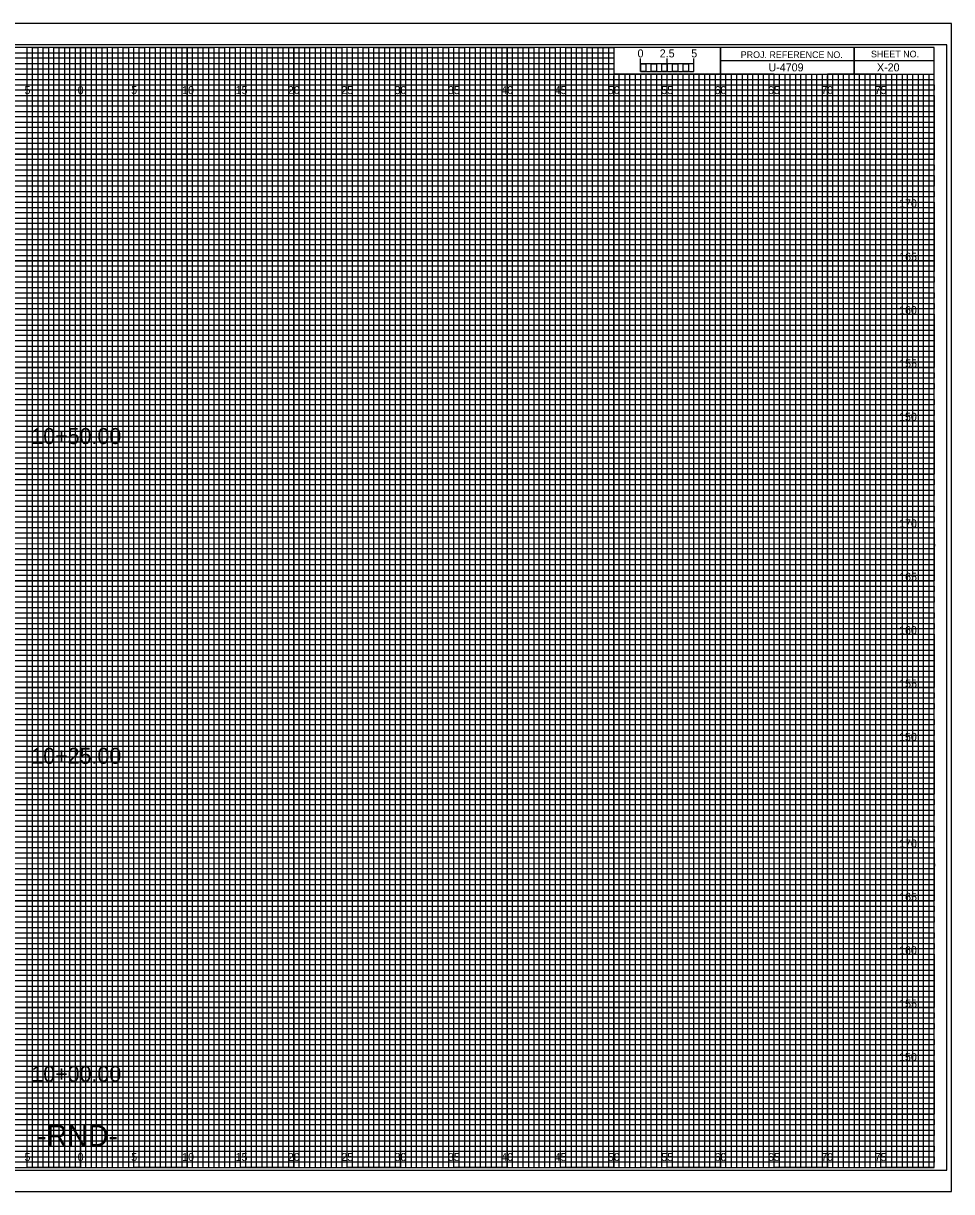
# Model space of a CAD drawing. Extents: x -7 to 162, y -2 to 107.
# Drawn here: x 74.6 to 161.7, y -2.3 to 107.3 of the extents above; entities that cross this region are included whole.
import ezdxf

# ---------------------------------------------------------------- set-up
doc = ezdxf.new("R2010")
doc.units = 0
for name, color, linetype in [('Prop XS Alignment Label', 7, 'Continuous'), ('Prop XS Bar Scale Labels', 7, 'Continuous'), ('Prop XS Elevation Labels', 7, 'Continuous'), ('Prop XS Label Text', 7, 'Continuous'), ('Prop XS Project Number', 7, 'Continuous'), ('Prop XS Sheet Number', 7, 'Continuous'), ('Prop XS Station Labels', 7, 'Continuous'), ('Sheet Cross Section CELL', 7, 'Continuous'), ('Sheet Cross Section Grid Major CELL', 7, 'Continuous'), ('Sheet Cross Section Grid Middle CELL', 7, 'Continuous'), ('Sheet Cross Section Grid Minor 1 CELL', 7, 'Continuous'), ('Sheet Cross Section Grid Minor 2 CELL', 7, 'Continuous'), ('Sheet Cross Section Scale CELL', 7, 'Continuous'), ('Sheet Cutting Line CELL', 7, 'Continuous'), ('Sheet DOT Grid CELL', 7, 'Continuous'), ('Sheet Plot Border Inside CELL', 7, 'Continuous'), ('Sheet Plot Border Outside CELL', 7, 'Continuous')]:
    doc.layers.add(name, color=color, linetype=linetype)

msp = doc.modelspace()

# ---------------------------------------------------------------- linework, layer by layer
at = {"layer": 'Sheet Cross Section CELL'}
for p, q in [((152.5, 105), (152.5, 102.5)), ((152.5, 102.5), (152.5, 105)), ((160, 103.75), (140, 103.75)), ((140, 103.75), (140, 102.5)), ((140, 102.5), (160, 102.5))]:
    msp.add_line(p, q, dxfattribs=at)
for points in [[(160, 105), (0, 105), (0, 0), (160, 0)], [(140, 105), (130, 105), (130, 102.52), (140, 102.52)], [(160, 105), (140, 105), (140, 102.5), (160, 102.5)]]:
    msp.add_lwpolyline(points, close=True, dxfattribs=at)
at = {"layer": 'Sheet Cross Section Grid Major CELL'}
for p, q in [((75, 105), (70, 105)), ((75, 0), (75, 105)), ((85, 105), (80, 105)), ((80, 105), (80, 0)), ((85, 0), (85, 105)), ((95, 105), (90, 105)), ((90, 105), (90, 0)), ((95, 0), (95, 105)), ((105, 105), (100, 105)), ((100, 105), (100, 0)), ((105, 0), (105, 105)), ((115, 105), (110, 105)), ((110, 105), (110, 0)), ((115, 0), (115, 105)), ((125, 105), (120, 105)), ((120, 105), (120, 0)), ((125, 0), (125, 105)), ((130, 105), (130, 0)), ((135, 0), (135, 102.5)), ((145, 102.5), (140, 102.5)), ((140, 102.5), (140, 0)), ((145, 0), (145, 102.5)), ((155, 102.5), (150, 102.5)), ((150, 102.5), (150, 0)), ((155, 0), (155, 102.5)), ((80, 0), (75, 0)), ((90, 0), (85, 0)), ((100, 0), (95, 0)), ((110, 0), (105, 0)), ((120, 0), (115, 0)), ((130, 0), (125, 0)), ((140, 0), (135, 0)), ((150, 0), (145, 0)), ((160, 0), (155, 0)), ((160, 0), (160, 0))]:
    msp.add_line(p, q, dxfattribs=at)
for points in [[(0, 100), (160, 100), (160, 95), (0, 95)], [(0, 90), (160, 90), (160, 85), (0, 85)], [(0, 80), (160, 80), (160, 75), (0, 75)], [(0, 70), (160, 70), (160, 65), (0, 65)], [(0, 60), (160, 60), (160, 55), (0, 55)], [(0, 50), (160, 50), (160, 45), (0, 45)], [(0, 40), (160, 40), (160, 35), (0, 35)], [(0, 30), (160, 30), (160, 25), (0, 25)], [(0, 20), (160, 20), (160, 15), (0, 15)], [(0, 10), (160, 10), (160, 5), (0, 5)]]:
    msp.add_lwpolyline(points, dxfattribs=at)
at = {"layer": 'Sheet Cross Section Grid Middle CELL'}
for points in [[(72.5, 0), (77.5, 0), (77.5, 105), (82.5, 105), (82.5, 0), (87.5, 0), (87.5, 105), (92.5, 105), (92.5, 0), (97.5, 0), (97.5, 105), (102.5, 105), (102.5, 0), (107.5, 0), (107.5, 105), (112.5, 105), (112.5, 0), (117.5, 0), (117.5, 105), (122.5, 105), (122.5, 0), (127.5, 0), (127.5, 105), (129.97, 105), (130, 105), (130, 102.5), (132.5, 102.5), (132.5, 0), (137.5, 0), (137.5, 102.5), (142.5, 102.5), (142.5, 0), (147.5, 0), (147.5, 102.5), (152.5, 102.5), (152.5, 0), (157.5, 0), (157.5, 102.5)], [(0, 102.5), (137.5, 102.5)], [(0, 92.5), (160, 92.5), (160, 97.5), (0, 97.5)], [(0, 82.5), (160, 82.5), (160, 87.5), (0, 87.5)], [(0, 72.5), (160, 72.5), (160, 77.5), (0, 77.5)], [(0, 62.5), (160, 62.5), (160, 67.5), (0, 67.5)], [(0, 52.5), (160, 52.5), (160, 57.5), (0, 57.5)], [(0, 42.5), (160, 42.5), (160, 47.5), (0, 47.5)], [(0, 32.5), (160, 32.5), (160, 37.5), (0, 37.5)], [(0, 22.5), (160, 22.5), (160, 27.5), (0, 27.5)], [(0, 12.5), (160, 12.5), (160, 17.5), (0, 17.5)], [(0, 2.5), (160, 2.5), (160, 7.5), (0, 7.5)]]:
    msp.add_lwpolyline(points, dxfattribs=at)
at = {"layer": 'Sheet Cross Section Grid Minor 1 CELL'}
for p, q in [((0, 104.5), (130, 104.5)), ((130, 104.5), (130, 103.99)), ((130, 103.99), (0, 103.99)), ((0, 103.5), (130, 103.5)), ((130, 102.95), (0, 102.95)), ((130, 103.5), (130, 102.95)), ((0, 102), (160, 102))]:
    msp.add_line(p, q, dxfattribs=at)
for points in [[(0, 101.5), (135, 101.5), (160, 101.5), (160, 101), (0, 101)], [(0, 100.5), (160, 100.5), (160, 99.5), (0, 99.5)], [(0, 99), (160, 99), (160, 98.5), (0, 98.49)], [(0, 98), (160, 98), (160, 97), (0, 97)], [(0, 96.5), (160, 96.5), (160, 96), (0, 96)], [(0, 95.5), (160, 95.5), (160, 94.5), (0, 94.5)], [(0, 94), (160, 94), (160, 93.5), (0, 93.5)], [(0, 93), (160, 93), (160, 92), (0, 92)], [(0, 91.5), (160, 91.5), (160, 91), (0, 91)], [(0, 90.5), (160, 90.5), (160, 89.5), (0, 89.5)], [(0, 89), (160, 89), (160, 88.5), (0, 88.5)], [(0, 88), (160, 88), (160, 86.98), (160, 86.5), (160, 86), (0, 86)], [(0, 87), (160, 87), (160, 86.5), (0, 86.5)], [(0, 85.5), (160, 85.5), (160, 84.5), (0, 84.52)], [(0, 84.52), (160, 84.5), (160, 84), (0, 84)], [(0, 83.5), (160, 83.5), (160, 83), (0, 83)], [(0, 82), (160, 82), (160, 81.5), (0, 81.5)], [(0, 81), (160, 81), (160, 80.5), (0, 80.5)], [(-0.04, 79.45), (160, 79.45), (160, 78.94), (-0.04, 78.94)], [(0, 78.5), (160, 78.5), (160, 78), (0, 78)], [(0, 77), (160, 77), (160, 76.5), (0, 76.5)], [(0, 76), (160, 76), (160, 75.5), (0, 75.5)], [(0, 74.5), (160, 74.5), (160, 74), (0, 74)], [(0, 73.5), (160, 73.5), (160, 73), (0, 73)], [(0, 72), (160, 72), (160, 71.5), (0, 71.5)], [(0, 71), (160, 71), (160, 70.5), (0, 70.5)], [(0, 69.5), (160, 69.5), (160, 68.99), (0, 69)], [(0, 68.5), (160, 68.5), (160, 68), (0, 68)], [(0, 67), (160, 67), (160, 66.5), (0, 66.5)], [(0, 66), (160, 66), (160, 65.5), (0, 65.5)], [(0, 64.5), (160, 64.5), (160, 64), (0, 64)], [(0, 63.5), (160, 63.5), (160, 63), (0, 63)], [(0, 62), (160, 62), (160, 61.5), (0, 61.5)], [(0, 61), (160, 61), (160, 60.5), (0, 60.5)], [(0, 59.5), (160, 59.5), (160, 59), (0, 59)], [(0, 58.5), (160.03, 58.45), (160, 58), (0, 58)], [(0, 57), (160, 57), (160, 56.5), (0, 56.5)], [(0, 56), (160, 56), (160, 55.5), (0, 55.5)], [(0, 54.5), (160, 54.5), (160, 54), (0, 54)], [(0, 53.5), (160, 53.5), (160, 53), (0, 53)], [(0, 52), (160, 52), (160, 51.5), (0, 51.5)], [(0, 51), (160, 51), (160, 50.5), (0, 50.5)], [(0, 49.5), (160, 49.5), (160, 49), (0, 49)], [(0, 48.5), (160, 48.5), (160, 48), (0, 48)], [(0, 47), (160, 47), (160, 46.5), (0, 46.5)], [(0, 46), (160, 46), (160, 45.5), (0, 45.5)], [(0, 44.5), (160, 44.5), (160, 44), (0, 44)], [(0, 43.5), (160, 43.5), (160, 43), (0, 43)], [(0, 42), (160, 42), (160, 41.5), (0, 41.5)], [(0, 41), (160, 41), (160, 40.5), (0, 40.5)], [(0, 39.5), (160, 39.5), (160, 38.99), (0, 39)], [(0, 38.5), (160, 38.5), (160, 38), (0, 38)], [(0, 37), (160, 37), (160, 36.5), (0, 36.5)], [(0, 36), (160, 36), (160, 35.5), (0, 35.5)], [(0, 34.5), (160, 34.5), (160, 34), (0, 34)], [(0, 33.5), (160, 33.5), (160, 33), (0, 33)], [(0, 32), (160, 32), (160, 31.5), (0, 31.5)], [(0, 31), (160, 31), (160, 30.5), (0, 30.5)], [(0, 29.5), (160, 29.5), (160, 29), (0, 29)], [(0, 28.5), (160.03, 28.46), (160, 28), (0, 28)], [(0, 27), (160, 27), (160, 26.5), (0, 26.5)], [(0, 26), (160, 26), (160, 25.5), (0, 25.5)], [(0, 24.5), (160, 24.5), (160, 24), (0, 24)], [(0, 23.5), (160, 23.5), (160, 23), (0, 23)], [(0, 22), (160, 22), (160, 21.5), (0, 21.5)], [(0, 21), (160, 21), (160, 20.5), (0, 20.5)], [(0, 19.5), (160, 19.5), (160, 19), (0, 19)], [(0, 18.5), (160, 18.5), (160, 18), (0, 18)], [(0, 17), (160, 17), (160, 16.5), (0, 16.5)], [(0, 16), (160, 16), (160, 15.5), (0, 15.5)], [(0, 14.5), (160, 14.5), (160, 14), (0, 14)], [(0, 13.5), (160, 13.5), (160, 13), (0, 13)], [(0, 12), (160, 12), (160, 11.5), (0, 11.5)], [(0, 11), (160, 11), (160, 10.5), (0, 10.5)], [(0, 9.5), (160, 9.5), (160, 9), (0, 9)], [(0, 8.5), (160, 8.5), (160, 8), (0, 8)], [(0, 7), (160, 7), (160, 6.5), (0, 6.5)], [(0, 6), (160, 6), (160, 5.5), (0, 5.5)], [(0, 4.5), (160, 4.5), (160, 4), (0, 4)], [(0, 3.5), (160, 3.5), (160, 3), (0, 3)], [(0, 2), (160, 2), (160, 1.5), (0, 1.5)], [(0, 1), (160, 1), (160, 0.5), (0, 0.5)]]:
    msp.add_lwpolyline(points, dxfattribs=at)
at = {"layer": 'Sheet Cross Section Grid Minor 2 CELL'}
for p, q in [((133.5, 102.5), (133, 102.5)), ((133, 102.5), (133, 0)), ((133.5, 0), (133.5, 102.5)), ((134.5, 102.5), (134, 102.5)), ((134, 102.5), (134, 0)), ((134.5, 0), (134.5, 102.5)), ((133, 0), (132.5, 0)), ((134, 0), (133.5, 0))]:
    msp.add_line(p, q, dxfattribs=at)
for points in [[(75, 0), (75.5, 0), (75.5, 105), (76, 105), (76, 0)], [(76, 0), (76.5, 0), (76.5, 105), (77, 105), (77, 0)], [(77.5, 0), (78, 0), (78, 105), (78.5, 105), (78.5, 0)], [(78.5, 0), (79, 0), (79, 105), (79.5, 105), (79.5, 0)], [(80, 0), (80.5, 0), (80.5, 105), (81, 105), (81, 0)], [(81, 0), (81.5, 0), (81.5, 105), (82, 105), (82, 0)], [(82.5, 0), (83, 0), (83, 105), (83.5, 105), (83.5, 0)], [(83.5, 0), (84, 0), (84, 105), (84.5, 105), (84.5, 0)], [(85, 0), (85.5, 0), (85.5, 105), (86, 105), (86, 0)], [(86, 0), (86.5, 0), (86.5, 105), (87, 105), (87, 0)], [(87.5, 0), (88, 0), (88, 105), (88.5, 105), (88.5, 0)], [(88.5, 0), (89, 0), (89, 105), (89.5, 105), (89.5, 0)], [(90, 0), (90.5, 0), (90.5, 105), (91, 105), (91, 0)], [(91, 0), (91.5, 0), (91.5, 105), (92, 105), (92, 0)], [(92.5, 0), (93, 0), (93, 105), (93.5, 105), (93.5, 0)], [(93.5, 0), (94, 0), (94, 105), (94.5, 105), (94.5, 0)], [(95, 0), (95.5, 0), (95.5, 105), (96, 105), (96, 0)], [(96, 0), (96.5, 0), (96.5, 105), (97, 105), (97, 0)], [(97.5, 0), (98, 0), (98, 105), (98.5, 105), (98.5, 0)], [(98.5, 0), (99, 0), (99, 105), (99.5, 105), (99.5, 0)], [(100, 0), (100.5, 0), (100.5, 105), (101, 105), (101, 0)], [(101, 0), (101.5, 0), (101.5, 105), (102, 105), (102, 0)], [(102.5, 0), (103, 0), (103, 105), (103.5, 105), (103.5, 0)], [(103.5, 0), (104, 0), (104, 105), (104.5, 105), (104.5, 0)], [(105, 0), (105.5, 0), (105.5, 105), (106, 105), (106, 0)], [(106, 0), (106.5, 0), (106.5, 105), (107, 105), (107, 0)], [(107.5, 0), (108, 0), (108, 105), (108.5, 105), (108.5, 0)], [(108.5, 0), (109, 0), (109, 105), (109.5, 105), (109.5, 0)], [(110, 0), (110.5, 0), (110.5, 105), (111, 105), (111, 0)], [(111, 0), (111.5, 0), (111.5, 105), (112, 105), (112, 0)], [(112.5, 0), (113, 0), (113, 105), (113.5, 105), (113.5, 0)], [(113.5, 0), (114, 0), (114, 105), (114.5, 105), (114.5, 0)], [(115, 0), (115.5, 0), (115.5, 105), (116, 105), (116, 0)], [(116, 0), (116.5, 0), (116.5, 105), (117, 105), (117, 0)], [(117.5, 0), (118, 0), (118, 105), (118.5, 105), (118.5, 0)], [(118.5, 0), (119, 0), (119, 105), (119.5, 105), (119.5, 0)], [(120, 0), (120.5, 0), (120.5, 105), (121, 105), (121, 0)], [(121, 0), (121.5, 0), (121.5, 105), (122, 105), (122, 0)], [(122.5, 0), (123, 0), (123, 105), (123.5, 105), (123.5, 0)], [(123.5, 0), (124, 0), (124, 105), (124.5, 105), (124.5, 0)], [(125, 0), (125.5, 0), (125.5, 105), (126, 105), (126, 0)], [(126, 0), (126.5, 0), (126.5, 105), (127, 105), (127, 0)], [(127.5, 0), (128, 0), (128, 105), (128.5, 105), (128.5, 0)], [(128.5, 0), (129, 0), (129, 105), (129.5, 105), (129.5, 0)], [(130, 0), (130.5, 0), (130.5, 102.5), (131.01, 102.5), (131.01, 0)], [(131, 0), (131.5, 0), (131.5, 102.5), (132, 102.5), (132, 0)], [(135, 0), (135.49, 0), (135.49, 102.5), (136, 102.5), (136, 0)], [(136, 0), (136.5, 0), (136.5, 102.5), (137.03, 102.5), (137.03, 0)], [(137.5, 0), (138, 0), (138, 102.5), (138.5, 102.5), (138.5, 0)], [(138.5, 0), (139, 0), (139, 102.5), (139.5, 102.5), (139.5, 0)], [(140, 0), (140.5, 0), (140.5, 102.5), (141, 102.5), (141, 0)], [(141, 0), (141.5, 0), (141.5, 102.5), (142, 102.5), (142, 0)], [(142.5, 0), (143, 0), (143, 102.5), (143.5, 102.5), (143.5, 0)], [(143.5, 0), (144, 0), (144, 102.5), (144.5, 102.5), (144.5, 0)], [(145, 0), (145.5, 0), (145.5, 102.5), (146, 102.5), (146, 0)], [(146, 0), (146.5, 0), (146.5, 102.5), (147, 102.5), (147, 0)], [(147.5, 0), (148, 0), (148, 102.5), (148.5, 102.5), (148.5, 0)], [(148.5, 0), (149, 0), (149, 102.5), (149.5, 102.5), (149.5, 0)], [(150, 0), (150.5, 0), (150.5, 102.5), (151, 102.5), (151, 0)], [(151, 0), (151.5, 0), (151.5, 102.5), (152, 102.5), (152, 0)], [(152.5, 0), (153, 0), (153, 102.5), (153.5, 102.5), (153.5, 0)], [(153.5, 0), (154, 0), (154, 102.5), (154.5, 102.5), (154.5, 0)], [(155, 0), (155.5, 0), (155.5, 102.5), (156, 102.5), (156, 0)], [(156, 0), (156.5, 0), (156.5, 102.5), (157, 102.5), (157, 0)], [(157.5, 0), (158, 0), (158, 102.5), (158.5, 102.5), (158.5, 0)], [(158.5, 0), (159, 0), (159, 102.5), (159.5, 102.5), (159.5, 0)]]:
    msp.add_lwpolyline(points, dxfattribs=at)
at = {"layer": 'Sheet Cross Section Scale CELL'}
for p, q in [((132.5, 102.75), (132.5, 103.95)), ((132.5, 103.45), (132.5, 103.95)), ((135, 102.75), (135, 103.95)), ((137.5, 102.75), (137.5, 103.95)), ((137.5, 103.45), (137.5, 103.95))]:
    msp.add_line(p, q, dxfattribs=at)
for points in [[(137.5, 103.45), (132.5, 103.45), (132.5, 102.75), (137.5, 102.75)], [(132.5, 103.45), (133, 103.45), (133, 102.75), (132.5, 102.75)], [(133.5, 103.45), (134, 103.45), (134, 102.75), (133.5, 102.75)], [(134.5, 103.45), (135, 103.45), (135, 102.75), (134.5, 102.75)], [(135.5, 103.45), (136, 103.45), (136, 102.75), (135.5, 102.75)], [(136.5, 103.45), (137, 103.45), (137, 102.75), (136.5, 102.75)]]:
    msp.add_lwpolyline(points, close=True, dxfattribs=at)
at = {"layer": 'Sheet Cutting Line CELL'}
for p, q in [((161.65, 107.25), (-6.7, 107.25)), ((-6.7, -2.25), (161.65, -2.25))]:
    msp.add_line(p, q, dxfattribs=at)
at = {"layer": 'Sheet DOT Grid CELL'}
for p, q in [((75, 0), (75, 105)), ((80, 0), (80, 105)), ((85, 0), (85, 105)), ((90, 0), (90, 105)), ((95, 0), (95, 105)), ((100, 0), (100, 105)), ((105, 0), (105, 105)), ((110, 0), (110, 105)), ((115, 0), (115, 105)), ((120, 0), (120, 105)), ((125, 0), (125, 105)), ((130, 0), (130, 102.34)), ((135, 0), (135, 102.34)), ((140, 0), (140, 102.34)), ((145, 0), (145, 102.34)), ((150, 0), (150, 102.34)), ((155, 0), (155, 102.34)), ((0, 100), (160, 100)), ((0, 95), (160, 95)), ((0, 90), (160, 90)), ((0, 85), (160, 85)), ((0, 80), (160, 80)), ((0, 75), (160, 75)), ((0, 70), (160, 70)), ((0, 65), (160, 65)), ((0, 60), (160, 60)), ((0, 55), (160, 55)), ((0, 50), (160, 50)), ((0, 45), (160, 45)), ((0, 40), (160, 40)), ((0, 35), (160, 35)), ((0, 30), (160, 30)), ((0, 25), (160, 25)), ((0, 20), (160, 20)), ((0, 15), (160, 15)), ((0, 10), (160, 10)), ((0, 5), (160, 5))]:
    msp.add_line(p, q, dxfattribs=at)
at = {"layer": 'Sheet Plot Border Inside CELL'}
msp.add_lwpolyline([(-5.4, -0.25), (161.2, -0.25), (161.2, 105.25), (-5.4, 105.25)], close=True, dxfattribs=at)
at = {"layer": 'Sheet Plot Border Outside CELL'}
msp.add_lwpolyline([(-6.7, -2.25), (161.65, -2.25), (161.65, 107.25), (-6.7, 107.25)], close=True, dxfattribs=at)

# ---------------------------------------------------------------- texts
at = {"layer": 'Prop XS Alignment Label'}
msp.add_text('-RND-', height=2, dxfattribs=at).set_placement((75.94, 2))
at = {"layer": 'Prop XS Bar Scale Labels'}
for s, p in [('2.5', (134.29, 104.06)), ('5', (137.24, 104.06))]:
    msp.add_text(s, height=0.75, dxfattribs=at).set_placement(p)
at = {"layer": 'Prop XS Elevation Labels'}
for s, p in [('170', (156.72, 90)), ('165', (156.73, 85)), ('160', (156.72, 80)), ('155', (156.73, 75)), ('150', (156.72, 70)), ('170', (156.72, 60)), ('165', (156.73, 55)), ('160', (156.72, 50)), ('155', (156.73, 45)), ('150', (156.72, 40)), ('170', (156.72, 30)), ('165', (156.73, 25)), ('160', (156.72, 20)), ('155', (156.73, 15)), ('150', (156.72, 10))]:
    msp.add_text(s, height=0.75, dxfattribs=at).set_placement(p)
at = {"layer": 'Prop XS Label Text'}
for s, p in [('5', (74.74, 100.62)), ('0', (79.73, 100.62)), ('0', (79.73, 100.62)), ('5', (84.74, 100.62)), ('10', (89.52, 100.62)), ('15', (94.53, 100.62)), ('20', (99.43, 100.62)), ('25', (104.44, 100.62)), ('30', (109.43, 100.62)), ('35', (114.44, 100.62)), ('40', (119.43, 100.62)), ('45', (124.44, 100.62)), ('50', (129.43, 100.62)), ('55', (134.44, 100.62)), ('60', (139.43, 100.62)), ('65', (144.44, 100.62)), ('70', (149.43, 100.62)), ('75', (154.44, 100.62)), ('5', (74.74, 0.62)), ('0', (79.73, 0.62)), ('0', (79.73, 0.62)), ('5', (84.74, 0.62)), ('10', (89.52, 0.62)), ('15', (94.53, 0.62)), ('20', (99.43, 0.62)), ('25', (104.44, 0.62)), ('30', (109.43, 0.62)), ('35', (114.44, 0.62)), ('40', (119.43, 0.62)), ('45', (124.44, 0.62)), ('50', (129.43, 0.62)), ('55', (134.44, 0.62)), ('60', (139.43, 0.62)), ('65', (144.44, 0.62)), ('70', (149.43, 0.62)), ('75', (154.44, 0.62))]:
    msp.add_text(s, height=0.75, dxfattribs=at).set_placement(p)
at = {"layer": 'Prop XS Project Number'}
msp.add_text('U-4709', height=0.75, dxfattribs=at).set_placement((144.48, 102.75))
at = {"layer": 'Prop XS Sheet Number'}
msp.add_text('X-20', height=0.75, dxfattribs=at).set_placement((154.65, 102.75))
at = {"layer": 'Prop XS Station Labels'}
for s, p in [('10+50.00', (75.39, 67.82)), ('10+25.00', (75.39, 37.85)), ('10+00.00', (75.39, 8.04))]:
    msp.add_text(s, height=1.5, dxfattribs=at).set_placement(p)
at = {"layer": 'Sheet Cross Section CELL'}
for s, p in [('PROJ. REFERENCE NO.', (141.88, 104)), ('SHEET NO.', (154.09, 104.06))]:
    msp.add_text(s, height=0.625, dxfattribs=at).set_placement(p)
at = {"layer": 'Sheet Cross Section Scale CELL'}
msp.add_text('0', height=0.75, dxfattribs=at).set_placement((132.21, 104.06))

doc.saveas('drawing.dxf')
